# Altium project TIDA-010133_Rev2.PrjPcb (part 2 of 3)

## Sheet 3_BUF802_OFFSET_TRIGGER.SchDoc: 3_BUF802_OFFSET_TRIGGER
size 431 x 279 mm; Date: Not shown in title block; ApprovedBy: Not shown in title block; CheckedBy: Not shown in title block; Author: Not shown in title block; CompanyName: Not shown in title block; DrawnBy: Rob Stoneham; Engineer: Not shown in title block; Organization: Not shown in title block; Address1: Not shown in title block; Address2: Not shown in title block; Address3: Not shown in title block; Address4: Not shown in title block; DocumentNumber: 4; Revision: Use project parameter SCH_Rev; SheetNumber: 4; SheetTotal: 8; PageSetup: Record=PageOptions¦CenterHorizontal=True¦CenterVertical=True¦PrintScale=1.00¦XCorrection=1.00¦YCorrection=1.00¦PrintKind=0¦BorderSize=5000000¦LeftOffset=0¦BottomOffset=0¦Orientation=2¦PaperLength=1000¦PaperWidth=1000¦Scale=100¦PaperSource=15¦PrintQuality=600¦MediaType=1¦DitherType=10¦PaperKind=Letter¦PrintScaleMode=1
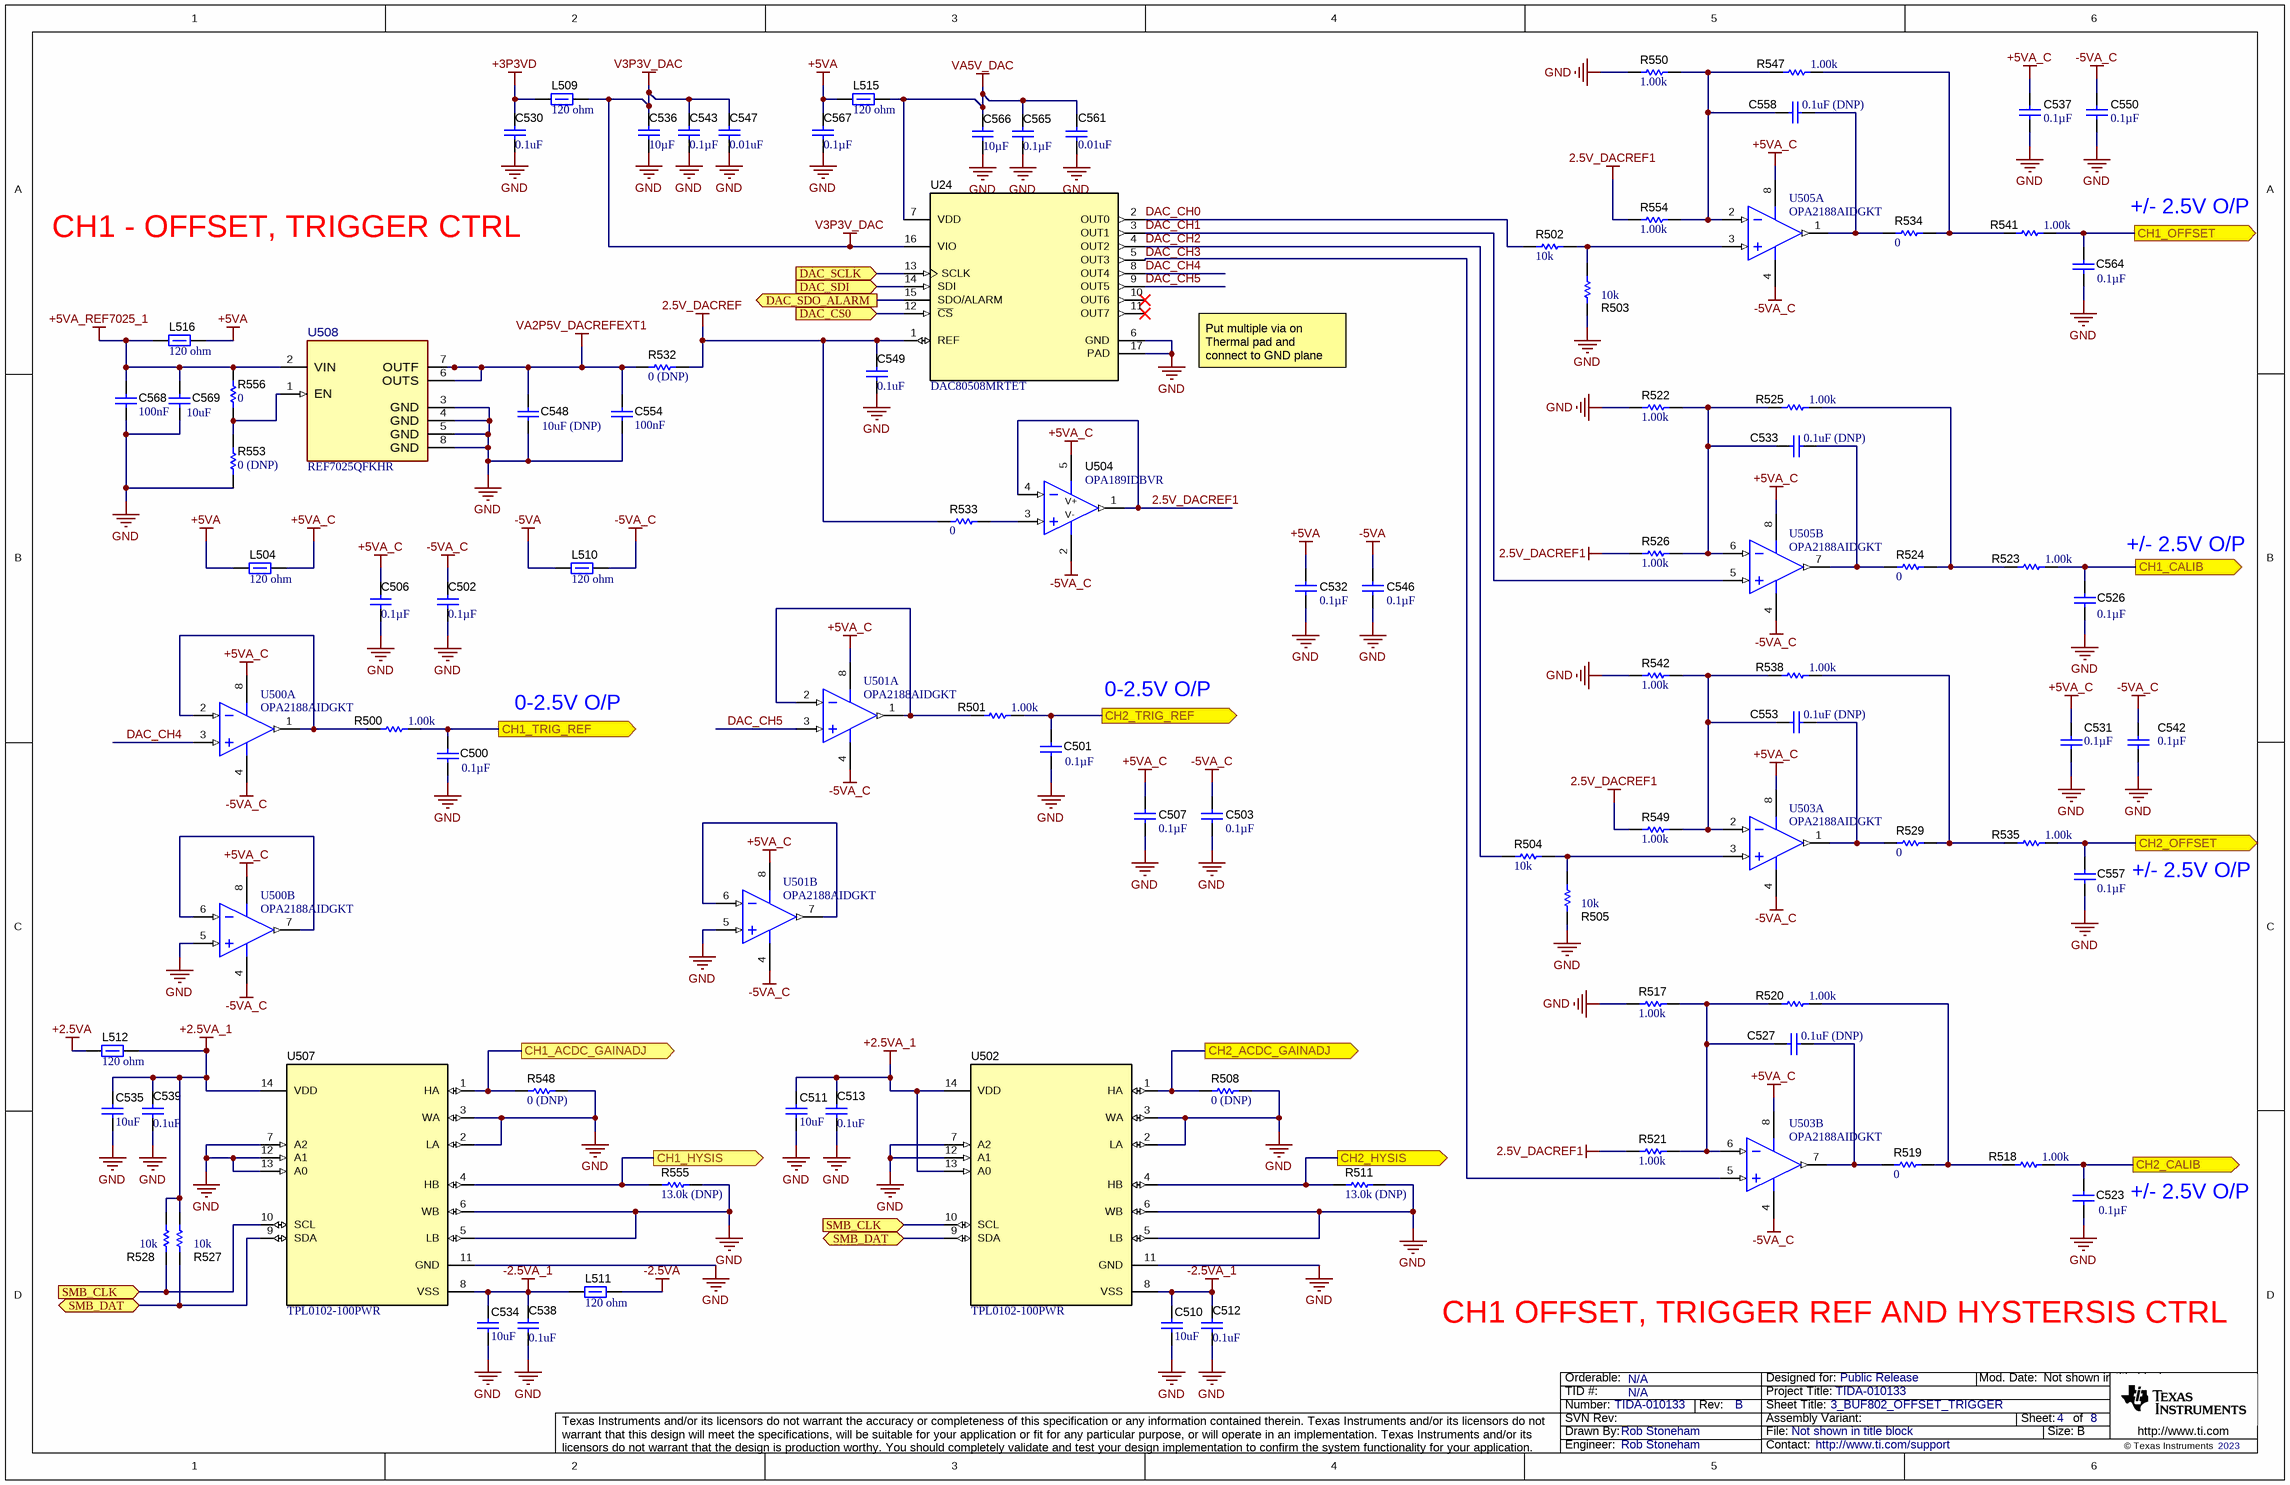
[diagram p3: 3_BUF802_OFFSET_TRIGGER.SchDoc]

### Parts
C500  ValueDisplayed: 0.1µF  [0402]  (hidden comment: 0402BB104KW500)
C501  ValueDisplayed: 0.1µF  [0402]  (hidden comment: 0402BB104KW500)
C502  ValueDisplayed: 0.1µF  [0402]  (hidden comment: 0402BB104KW500)
C503  ValueDisplayed: 0.1µF  [0402]  (hidden comment: 0402BB104KW500)
C506  ValueDisplayed: 0.1µF  [0402]  (hidden comment: 0402BB104KW500)
C507  ValueDisplayed: 0.1µF  [0402]  (hidden comment: 0402BB104KW500)
C510  ValueDisplayed: 10uF  [1206_190]  (hidden comment: C3216X7R1E106M160AE)
C511  ValueDisplayed: 10uF  [1206_190]  (hidden comment: C3216X7R1E106M160AE)
C512  ValueDisplayed: 0.1uF  [0603]  (hidden comment: CGA3E2X7R1H104K080AA)
C513  ValueDisplayed: 0.1uF  [0603]  (hidden comment: CGA3E2X7R1H104K080AA)
C523  ValueDisplayed: 0.1µF  [0402]  (hidden comment: 0402BB104KW500)
C526  ValueDisplayed: 0.1µF  [0402]  (hidden comment: 0402BB104KW500)
C527  ValueDisplayed: 0.1uF (DNP)  [0603]  (hidden comment: CGA3E2X7R1H104K080AA)
C530  ValueDisplayed: 0.1uF  [0603]  (hidden comment: CGA3E2X7R1H104K080AA)
C531  ValueDisplayed: 0.1µF  [0402]  (hidden comment: 0402BB104KW500)
C532  ValueDisplayed: 0.1µF  [0402]  (hidden comment: 0402BB104KW500)
C533  ValueDisplayed: 0.1uF (DNP)  [0603]  (hidden comment: CGA3E2X7R1H104K080AA)
C534  ValueDisplayed: 10uF  [1206_190]  (hidden comment: C3216X7R1E106M160AE)
C535  ValueDisplayed: 10uF  [1206_190]  (hidden comment: C3216X7R1E106M160AE)
C536  ValueDisplayed: 10µF  [0805_HV]  (hidden comment: CC0805KKX5R8BB106)
C537  ValueDisplayed: 0.1µF  [0402]  (hidden comment: 0402BB104KW500)
C538  ValueDisplayed: 0.1uF  [0603]  (hidden comment: CGA3E2X7R1H104K080AA)
C539  ValueDisplayed: 0.1uF  [0603]  (hidden comment: CGA3E2X7R1H104K080AA)
C542  ValueDisplayed: 0.1µF  [0402]  (hidden comment: 0402BB104KW500)
C543  ValueDisplayed: 0.1µF  [0402]  (hidden comment: 0402BB104KW500)
C546  ValueDisplayed: 0.1µF  [0402]  (hidden comment: 0402BB104KW500)
C547  ValueDisplayed: 0.01uF  [0402]  (hidden comment: GRM155R71H103KA88D)
C548  value 10uF (DNP)  [1206_180]  (hidden comment: C3216X7R1V106K160AC)
C549  ValueDisplayed: 0.1uF  [0603]  (hidden comment: CGA3E2X7R1H104K080AA)
C550  ValueDisplayed: 0.1µF  [0402]  (hidden comment: 0402BB104KW500)
C553  ValueDisplayed: 0.1uF (DNP)  [0603]  (hidden comment: CGA3E2X7R1H104K080AA)
C554  Cap_F: 100nF  [0603]  (hidden comment: C0603X104K4RACTU)
C557  ValueDisplayed: 0.1µF  [0402]  (hidden comment: 0402BB104KW500)
C558  ValueDisplayed: 0.1uF (DNP)  [0603]  (hidden comment: CGA3E2X7R1H104K080AA)
C561  ValueDisplayed: 0.01uF  [0402]  (hidden comment: GRM155R71H103KA88D)
C564  ValueDisplayed: 0.1µF  [0402]  (hidden comment: 0402BB104KW500)
C565  ValueDisplayed: 0.1µF  [0402]  (hidden comment: 0402BB104KW500)
C566  ValueDisplayed: 10µF  [0805_HV]  (hidden comment: CC0805KKX5R8BB106)
C567  ValueDisplayed: 0.1µF  [0402]  (hidden comment: 0402BB104KW500)
C568  Cap_F: 100nF  [0603]  (hidden comment: CGA3E2X7R1H104K080AA)
C569  ValueDisplayed: 10uF  [1206_180]  (hidden comment: C3216X7R1V106K160AC)
L504  ValueDisplayed: 120 ohm  [0603]  (hidden comment: BLM18SG121TN1D)
L509  ValueDisplayed: 120 ohm  [0603]  (hidden comment: BLM18SG121TN1D)
L510  ValueDisplayed: 120 ohm  [0603]  (hidden comment: BLM18SG121TN1D)
L511  ValueDisplayed: 120 ohm  [0603]  (hidden comment: BLM18SG121TN1D)
L512  ValueDisplayed: 120 ohm  [0603]  (hidden comment: BLM18SG121TN1D)
L515  ValueDisplayed: 120 ohm  [0603]  (hidden comment: BLM18SG121TN1D)
L516  ValueDisplayed: 120 ohm  [0603]  (hidden comment: BLM18SG121TN1D)
R500  ValueDisplayed: 1.00k  [0603]  (hidden comment: RC0603FR-071KL)
R501  ValueDisplayed: 1.00k  [0603]  (hidden comment: RC0603FR-071KL)
R502  ValueDisplayed: 10k  [0603]  (hidden comment: CRCW060310K0JNEA)
R503  ValueDisplayed: 10k  [0603]  (hidden comment: CRCW060310K0JNEA)
R504  ValueDisplayed: 10k  [0603]  (hidden comment: CRCW060310K0JNEA)
R505  ValueDisplayed: 10k  [0603]  (hidden comment: CRCW060310K0JNEA)
R508  ValueDisplayed: 0 (DNP)  [0603]  (hidden comment: CRCW06030000Z0EA)
R511  ValueDisplayed: 13.0k (DNP)  [0402L]  (hidden comment: CRCW040213K0FKED)
R517  ValueDisplayed: 1.00k  [0603]  (hidden comment: RC0603FR-071KL)
R518  ValueDisplayed: 1.00k  [0603]  (hidden comment: RC0603FR-071KL)
R519  ValueDisplayed: 0  [0603]  (hidden comment: RMCF0603ZT0R00)
R520  ValueDisplayed: 1.00k  [0603]  (hidden comment: RC0603FR-071KL)
R521  ValueDisplayed: 1.00k  [0603]  (hidden comment: RC0603FR-071KL)
R522  ValueDisplayed: 1.00k  [0603]  (hidden comment: RC0603FR-071KL)
R523  ValueDisplayed: 1.00k  [0603]  (hidden comment: RC0603FR-071KL)
R524  ValueDisplayed: 0  [0603]  (hidden comment: RMCF0603ZT0R00)
R525  ValueDisplayed: 1.00k  [0603]  (hidden comment: RC0603FR-071KL)
R526  ValueDisplayed: 1.00k  [0603]  (hidden comment: RC0603FR-071KL)
R527  ValueDisplayed: 10k  [0603]  (hidden comment: CRCW060310K0JNEA)
R528  ValueDisplayed: 10k  [0603]  (hidden comment: CRCW060310K0JNEA)
R529  ValueDisplayed: 0  [0603]  (hidden comment: RMCF0603ZT0R00)
R532  ValueDisplayed: 0 (DNP)  [0603]  (hidden comment: CRCW06030000Z0EA)
R533  ValueDisplayed: 0  [0603]  (hidden comment: CRCW06030000Z0EA)
R534  ValueDisplayed: 0  [0603]  (hidden comment: RMCF0603ZT0R00)
R535  ValueDisplayed: 1.00k  [0603]  (hidden comment: RC0603FR-071KL)
R538  ValueDisplayed: 1.00k  [0603]  (hidden comment: RC0603FR-071KL)
R541  ValueDisplayed: 1.00k  [0603]  (hidden comment: RC0603FR-071KL)
R542  ValueDisplayed: 1.00k  [0603]  (hidden comment: RC0603FR-071KL)
R547  ValueDisplayed: 1.00k  [0603]  (hidden comment: RC0603FR-071KL)
R548  ValueDisplayed: 0 (DNP)  [0603]  (hidden comment: CRCW06030000Z0EA)
R549  ValueDisplayed: 1.00k  [0603]  (hidden comment: RC0603FR-071KL)
R550  ValueDisplayed: 1.00k  [0603]  (hidden comment: RC0603FR-071KL)
R553  ValueDisplayed: 0 (DNP)  [0603]  (hidden comment: CRCW06030000Z0EA)
R554  ValueDisplayed: 1.00k  [0603]  (hidden comment: RC0603FR-071KL)
R555  ValueDisplayed: 13.0k (DNP)  [0402L]  (hidden comment: CRCW040213K0FKED)
R556  ValueDisplayed: 0  [0603]  (hidden comment: CRCW06030000Z0EA)
U24  DAC80508MRTET  [RTE0016D]
U500  OPA2188AIDGKT  [DGK0008A_N]  (parts A,B of 2)
U501  OPA2188AIDGKT  [DGK0008A_N]  (parts A,B of 2)
U502  TPL0102-100PWR  [PW0014A_N]
U503  OPA2188AIDGKT  [DGK0008A_N]  (parts A,B of 2)
U504  OPA189IDBVR  [DBV0005A_N]
U505  OPA2188AIDGKT  [DGK0008A_N]  (parts A,B of 2)
U507  TPL0102-100PWR  [PW0014A_N]
U508  REF7025QFKHR  [FKH0008A-MFG]

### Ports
CH1_ACDC_GAINADJ (out), CH1_CALIB (out), CH1_HYSIS (out), CH1_OFFSET (out), CH1_TRIG_REF (out), CH2_ACDC_GAINADJ (out), CH2_CALIB (out), CH2_HYSIS (out), CH2_OFFSET (out), CH2_TRIG_REF (out), DAC_CS0 (in), DAC_SCLK (in), DAC_SDI (in), DAC_SDO_ALARM (out), SMB_CLK (in), SMB_DAT (bidir)

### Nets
2.5V_DACREF: C549.1 R532.1 R533.2 U24.1(REF)
2.5V_DACREF1: R521.1 R526.1 R549.1 R554.1 U504.1(OUT) U504.4(IN-)
+2.5VA: L512.1
+2.5VA_1: C511.2 C513.1 C535.2 C539.1 L512.2 R527.2 R528.2 U502.13(A0) U502.14(VDD) U507.14(VDD)
+3P3VD: C530.1 L509.1
+5VA: C532.1 C567.1 L504.1 L515.1 L516.2
+5VA_C: C506.1 C507.1 C531.1 C537.1 L504.2 U500.8(V+) U501.8(V+) U503.8(V+) U504.5(V+) U505.8(V+)
+5VA_REF7025_1: C568.1 C569.1 L516.1 R556.2 U508.2(VIN)
-2.5VA: L511.2
-2.5VA_1: C510.2 C512.1 C534.2 C538.1 L511.1 U502.8(VSS) U507.8(VSS)
-5VA: C546.1 L510.1
-5VA_C: C502.1 C503.1 C542.1 C550.1 L510.2 U500.4(V-) U501.4(V-) U503.4(V-) U504.2(V-) U505.4(V-)
GND: C500.2 C501.2 C502.2 C503.2 C506.2 C507.2 C510.1 C511.1 C512.2 C513.2 C523.2 C526.2 C530.2 C531.2 C532.2 C534.1 C535.1 C536.2 C537.2 C538.2 C539.2 C542.2 C543.2 C546.2 C547.2 C548.2 C549.2 C550.2 C554.2 C557.2 C561.2 C564.2 C565.2 C566.2 C567.2 C568.2 C569.2 R503.1 R505.1 R508.2 R511.1 R517.1 R522.1 R542.1 R548.2 R550.1 R553.1 R555.1 U24.6(GND) U24.17(PAD) U500.5(IN_B+) U501.5(IN_B+) U502.2(LA) U502.3(WA) U502.5(LB) U502.6(WB) U502.7(A2) U502.11(GND) U502.12(A1) U507.2(LA) U507.3(WA) U507.5(LB) U507.6(WB) U507.7(A2) U507.11(GND) U507.12(A1) U507.13(A0) U508.3(GND) U508.4(GND) U508.5(GND) U508.8(GND)
V3P3V_DAC: C536.1 C543.1 C547.1 L509.2 U24.16(VIO)
VA2P5V_DACREFEXT1: C548.1 C554.1 R532.2 U508.6(OUTS) U508.7(OUTF)
VA5V_DAC: C561.1 C565.1 C566.1 L515.2 U24.7(VDD)
CH1_ACDC_GAINADJ: R548.1 U507.1(HA) ; port CH1_ACDC_GAINADJ
CH1_CALIB: C526.1 R523.2 ; port CH1_CALIB
CH1_HYSIS: R555.2 U507.4(HB) ; port CH1_HYSIS
CH1_OFFSET: C564.1 R541.2 ; port CH1_OFFSET
CH1_TRIG_REF: C500.1 R500.2 ; port CH1_TRIG_REF
CH2_ACDC_GAINADJ: R508.1 U502.1(HA) ; port CH2_ACDC_GAINADJ
CH2_CALIB: C523.1 R518.2 ; port CH2_CALIB
CH2_HYSIS: R511.2 U502.4(HB) ; port CH2_HYSIS
CH2_OFFSET: C557.1 R535.2 ; port CH2_OFFSET
CH2_TRIG_REF: C501.1 R501.2 ; port CH2_TRIG_REF
DAC_CH0: R502.2 U24.2(OUT0)
DAC_CH1: U24.3(OUT1) U505.5(IN_B+)
DAC_CH2: R504.2 U24.4(OUT2)
DAC_CH3: U24.5(OUT3) U503.5(IN_B+)
DAC_CH4: U24.8(OUT4) U500.3(IN_A+)
DAC_CH5: U24.9(OUT5) U501.3(IN_A+)
DAC_CS0: U24.12(~{CS}) ; port DAC_CS0
DAC_SCLK: U24.13(SCLK) ; port DAC_SCLK
DAC_SDI: U24.14(SDI) ; port DAC_SDI
DAC_SDO_ALARM: U24.15(SDO/ALARM) ; port DAC_SDO_ALARM
SMB_CLK: R528.1 U502.10(SCL) U507.10(SCL) ; port SMB_CLK
SMB_DAT: R527.1 U502.9(SDA) U507.9(SDA) ; port SMB_DAT
NetC527_1: C527.1 R517.2 R520.1 R521.2 U503.6(IN_B-)
NetC527_2: C527.2 R519.1 U503.7(OUT_B)
NetC533_1: C533.1 R522.2 R525.1 R526.2 U505.6(IN_B-)
NetC533_2: C533.2 R524.1 U505.7(OUT_B)
NetC553_1: C553.1 R538.1 R542.2 R549.2 U503.2(IN_A-)
NetC553_2: C553.2 R529.1 U503.1(OUT_A)
NetC558_1: C558.1 R547.1 R550.2 R554.2 U505.2(IN_A-)
NetC558_2: C558.2 R534.1 U505.1(OUT_A)
NetR500_1: R500.1 U500.1(OUT_A) U500.2(IN_A-)
NetR501_1: R501.1 U501.1(OUT_A) U501.2(IN_A-)
NetR502_1: R502.1 R503.2 U505.3(IN_A+)
NetR504_1: R504.1 R505.2 U503.3(IN_A+)
NetR518_1: R518.1 R519.2 R520.2
NetR523_1: R523.1 R524.2 R525.2
NetR529_2: R529.2 R535.1 R538.2
NetR533_1: R533.1 U504.3(IN+)
NetR534_2: R534.2 R541.1 R547.2
NetR553_2: R553.2 R556.1 U508.1(EN)
NetU500_6: U500.6(IN_B-) U500.7(OUT_B)
NetU501_6: U501.6(IN_B-) U501.7(OUT_B)

Not connected (* = marked no-connect by the designer): U24 10(OUT6)* 11(OUT7)*

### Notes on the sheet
- CH1 - OFFSET, TRIGGER CTRL
- +/- 2.5V O/P
- Put multiple via on Thermal pad and connect to GND plane
- 0-2.5V O/P
- (near C557) +/- 2.5V O/P
- (near C523) +/- 2.5V O/P
- CH1 OFFSET, TRIGGER REF AND HYSTERSIS CTRL

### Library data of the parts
C500-C503 C506 C507 C523 C526 C531 C532 C537 C542 C543 C546 C550 C557 C564 C565 C567 = CMP-0860983-1: CAP, CERM, 0.1 µF, 50 V,+/- 10%, X7R, 0402; Manufacturer: Passive Plus; TaMax_C: 125°C; VDC_V: 50V; U/M: EA; SizeY_mm: 0.5; TaMin_C: -55°C; SizeAreaWB_mm2: 3; Value: 0.1uF; AEC Qualified: N; SizeX_mm: 1; AEC Category: Q200; SizeZ_mm: 0.6; Cap_F: 100nF
C510 C511 C534 C535 = CMP-0008692-2: CAP, CERM, 10 uF, 25 V, +/- 20%, X7R, 1206_190; Manufacturer: TDK; Polarized: N; Value: 10uF; U/M: EA; Cap_F: 10µF; Value1: Unknown; VDC_V: 25V; TaMin_C: -55°C; TaMax_C: 125°C; Cap_Case: 1206; SizeArea_mm2: 5.12; SizeAreaWB_mm2: 10.92; SizeX_mm: 3.2; SizeY_mm: 1.6; SizeZ_mm: 1.9; AEC Category: Q200
C512 C513 C527 C530 C533 C538 C539 C549 C553 C558 = CMP-0007078-4: CAP, CERM, 0.1 uF, 50 V, +/- 10%, X7R, AEC-Q200 Grade 1, 0603; Manufacturer: TDK; Polarized: N; Value: 0.1uF; U/M: EA; Cap_F: 100nF; ESR_ohm: 29.6m; Value1: 0.0296 ohm; VDC_V: 50V; IRMS_A: 971.99mA; TaMin_C: -55°C; TaMax_C: 125°C; SizeArea_mm2: 1.28; SizeAreaWB_mm2: 4.68; SizeX_mm: 1.6; SizeY_mm: 0.8; SizeZ_mm: 1; AEC Category: Q200; AEC Qualified: Y
C536 C566 = CMP-0084177-1: CAP, CERM, 10 µF, 25 V,+/- 10%, X5R, 0805; Manufacturer: Yageo; SizeAreaWB_mm2: 6.75; SizeArea_mm2: 2.5; AEC Qualified: N; AEC Category: Q200; Value: 10uF; TaMax_C: 85°C; SizeZ_mm: 1.45; TaMin_C: -55°C; VDC_V: 25V; SizeY_mm: 1.25; U/M: EA; SizeX_mm: 2; Cap_Case: 0805
C547 C561 = CMP-0006674-2: CAP, CERM, 0.01 uF, 50 V, +/- 10%, X7R, 0402; Manufacturer: MuRata; TaMin_C: -55°C; Polarized: N; SizeAreaWB_mm2: 3; Value1: Unknown; U/M: EA; Value: 0.01uF; TaMax_C: 125°C; SizeZ_mm: 0.6; SizeX_mm: 1; SizeY_mm: 0.5; Value2: 50V; Cap_F: 10nF; AEC Category: Q200
C548 = CMP-0008705-2: CAP, CERM, 10 uF, 35 V, +/- 10%, X7R, 1206; Manufacturer: TDK; TaMin_C: -55°C; Polarized: N; SizeAreaWB_mm2: 10.92; Value1: 0.002229 ohm; U/M: EA; TaMax_C: 125°C; SizeZ_mm: 1.8; SizeX_mm: 3.2; SizeY_mm: 1.6; Value2: 35V; SizeArea_mm2: 5.12; Cap_F: 10µF; AEC Category: Q200; ValueDisplayed: 10uF; ESR_ohm: 2.229m; IRMS_A: 4.8593A
C554 = CMP-0006980-4: CAP, CERM, 0.1 uF, 16 V, +/- 10%, X7R, 0603; Manufacturer: Kemet; TaMin_C: -55°C; Polarized: N; SizeAreaWB_mm2: 4.68; Value1: Unknown; U/M: EA; Value: 0.1uF; TaMax_C: 125°C; SizeZ_mm: 1; SizeX_mm: 1.6; SizeY_mm: 0.8; Value2: 16V; SizeArea_mm2: 1.28; AEC Category: Q200
C568 = CMP-0007078-4: CAP, CERM, 0.1 uF, 50 V, +/- 10%, X7R, AEC-Q200 Grade 1, 0603; Manufacturer: TDK; TaMin_C: -55°C; ESR_ohm: 29.6m; Polarized: N; SizeAreaWB_mm2: 4.68; Value1: 0.0296 ohm; U/M: EA; Value: 0.1uF; TaMax_C: 125°C; SizeZ_mm: 1; SizeX_mm: 1.6; SizeY_mm: 0.8; Value2: 50V; SizeArea_mm2: 1.28; AEC Qualified: Y; IRMS_A: 971.99mA; AEC Category: Q200
C569 = CMP-0008705-2: CAP, CERM, 10 uF, 35 V, +/- 10%, X7R, 1206; Manufacturer: TDK; TaMin_C: -55°C; Polarized: N; SizeAreaWB_mm2: 10.92; Value1: 0.002229 ohm; U/M: EA; Value: 10uF; TaMax_C: 125°C; SizeZ_mm: 1.8; SizeX_mm: 3.2; SizeY_mm: 1.6; Value2: 35V; SizeArea_mm2: 5.12; Cap_F: 10µF; AEC Category: Q200; ESR_ohm: 2.229m; IRMS_A: 4.8593A
L504 L509-L512 L515 L516 = CMP-0003352-2: Ferrite Bead, 120 ohm @ 100 MHz, 3 A, 0603; Manufacturer: MuRata; Value: 120 ohm; Imax_A: 3A; DCR_ohm: 25m; Value1: 0.025 ohm; SizeAreaWB_mm2: 4.68; SizeArea_mm2: 1.28; SizeX_mm: 1.6; SizeY_mm: 0.8; SizeZ_mm: 1; ZTyp@100MHz_Ohm: 120
R500 R501 R517 R518 R520-R523 R525 R526 R535 R538 R541 R542 R547 R549 R550 R554 = CMP-0022895-5: RES, 1.00 k, 1%, 0.1 W, 0603; Manufacturer: Yageo; Power_W: 100mW; TempCo: 100 ppm/C; Value_Code: 1k00; Value: 1.00k; EIA_Code: E96; Res_ohm: 1k; SizeX_mm: 1.6; SizeY_mm: 0.8; SizeZ_mm: 1; Value2: 0.1W; SizeArea_mm2: 1.28; AEC Qualified: N; VDC_V: 75V; AEC Category: Q200; SizeAreaWB_mm2: 4.68
R502-R505 R527 R528 = CMP-0025701-4: RES, 10 k, 5%, 0.1 W, AEC-Q200 Grade 0, 0603; Manufacturer: Vishay-Dale; Value: 10k; Value_Code: 10k0; Power_W: 100mW; Value2: 0.1W; VDC_V: 75V; TempCo: 200 ppm/C; SizeArea_mm2: 1.28; SizeX_mm: 1.6; SizeY_mm: 0.8; SizeZ_mm: 1; EIA_Code: E24; AEC Category: Q200; AEC Qualified: Y; AEC Grade: 0
R508 R548 = CMP-0025697-4: RES, 0, 5%, 0.1 W, AEC-Q200 Grade 0, 0603; Manufacturer: Vishay-Dale; Power_W: 100mW; TempCo: 200 ppm/C; Value_Code: 0000; Value: 0; EIA_Code: E24; SizeX_mm: 1.6; SizeY_mm: 0.8; SizeZ_mm: 1; Value2: 0.1W; SizeArea_mm2: 1.28; AEC Qualified: Y; VDC_V: 75V; AEC Category: Q200
R511 R555 = CMP-0026003-3: RES, 13.0 k, 1%, 0.063 W, AEC-Q200 Grade 0, 0402; Manufacturer: Vishay-Dale; Power_W: 63mW; TempCo: 100 ppm/C; Value_Code: 13k0; Value: 13.0k; EIA_Code: E96; Res_ohm: 13k; SizeX_mm: 1; SizeY_mm: 0.5; SizeZ_mm: 0.6; Value2: 0.063W; AEC Qualified: Y; VDC_V: 50V; AEC Category: Q200; AEC Grade: 0
R519 R524 R529 R534 = CMP-0023343-3: RES, 0, 1%, 0.1 W, AEC-Q200 Grade 0, 0603; Manufacturer: Stackpole Electronics Inc; Power_W: 100mW; TempCo: ppm/C; U/M: EA; Value: 0; SizeX_mm: 1.6; SizeY_mm: 0.8; SizeZ_mm: 1; Value2: 0.1W; SizeArea_mm2: 1.28; AEC Qualified: Y; AEC Category: Q200
R532 R533 R553 R556 = CMP-0025697-4: RES, 0, 5%, 0.1 W, AEC-Q200 Grade 0, 0603; Manufacturer: Vishay-Dale; Value: 0; Value_Code: 0000; Power_W: 100mW; Value2: 0.1W; VDC_V: 75V; TempCo: 200 ppm/C; SizeArea_mm2: 1.28; SizeX_mm: 1.6; SizeY_mm: 0.8; SizeZ_mm: 1; EIA_Code: E24; AEC Category: Q200; AEC Qualified: Y
U24 = CMP-0084837-1: 8-Channel, True 16-Bit, SPI, Voltage-Output DAC With Precision Internal Reference, RTE0016D (WQFN-16); Alternate PartNumber: DAC80508MRTER; Alternate Manufacturer: Texas Instruments; CompType: IC; SizeAreaWB_mm2: 16; AEC Qualified: N; AEC Category: Q200; Rating: Catalog; SizeY_mm: 3; SizeZ_mm: 0.8; SizeArea_mm2: 9
U500 U501 U503 U505 = CMP-0040605-2: 0.03µV/°C, 6µV Vos, Low Noise, Rail-to-Rail Output, 36V Zero-Drift Operational Amplifier, DGK0008A (VSSOP-8); Manufacturer: Texas Instruments; Rating: Catalog; Vio (25C)(Max)(mV): 0.025; Number of Channels: 2; Slew Rate(Typ)(V/us): 0.8; IIB(Max)(pA): 850; Offset Drift(Typ)(uV/C): 0.03; Sub Family: High Supply Voltage Amplifier (>=30V), Low Noise Amp (<=10nV/rtHz), Low Offset Voltage Amplifier (<=500uV), Low Power Amp (<=500uA), Precision Amplifier, Zero Drift Precision Amplifier; CMRR(Min)(dB): 120; Total Supply Voltage(Max)(+5V is 5, +/-5V is 10): 36; Iq per channel(Max)(mA): 0.475; Total Supply Voltage(Min)(+5V is 5, +/-5V is 10): 4; Eco-Plan: Green (RoHS & no Sb/Br); Packing: SMALL T&R; AEC Category: Q200; AEC Qualified: N; CompType: IC; SizeAreaWB_mm2: 23.6; SizeArea_mm2: 14.7; SizeX_mm: 4.9; SizeY_mm: 3; SizeZ_mm: 1.1
U502 U507 = CMP-0066591-1: 256-Taps Dual-Channel Digital Potentiometer With I2C Interface and Nonvolatile Memory, PW0014A (TSSOP-14); Alternate Manufacturer: Texas Instruments; SizeAreaWB_mm2: 58.8; U/M: EA; SizeZ_mm: 1.2; SizeX_mm: 6.4; SizeY_mm: 5.0; SizeArea_mm2: 32.0; CompType: IC
U504 = CMP-0860961-1: 14MHz, MUX-friendly, low-noise, zero-drift, RRO, CMOS precision operational amplifier, DBV0005A (SOT-23-5); Alternate Manufacturer: Texas Instruments; Alternate PartNumber: OPA189IDBVT; SizeY_mm: 2.9; AEC Qualified: N; SizeX_mm: 2.8; SizeAreaWB_mm2: 14.82; CompType: IC; SizeZ_mm: 1.45; Rating: Catalog; AEC Category: Q200; SizeArea_mm2: 8.12
U508 = CMP-0091880-1: 2 ppm/°C Maximum Drift, 0.23 ppmp-p 1/f Noise, Precision Voltage Reference; Manufacturer: Texas Instruments; Number Of Outputs: 1; Output Voltage: 2.5V; Switching Topology: Buck; Output Type: Fixed; Max Supply Voltage: 18V; Nominal Supply Current: 4mA; SizeZ_mm: 1.6mm; TaMax_C: +125°C; TaMin_C: -40°C; Min Supply Voltage: 3V; AEC Qualified: No

## Sheet 4_BUF802_USBIF.SchDoc: 4_BUF802_USBIF
size 431 x 279 mm; Date: Not shown in title block; ApprovedBy: Not shown in title block; CheckedBy: Not shown in title block; Author: Not shown in title block; CompanyName: Not shown in title block; DrawnBy: Rob Stoneham; Engineer: Not shown in title block; Organization: Not shown in title block; Address1: Not shown in title block; Address2: Not shown in title block; Address3: Not shown in title block; Address4: Not shown in title block; DocumentNumber: 5; Revision: Use project parameter SCH_Rev; SheetNumber: 5; SheetTotal: 8; PageSetup: Record=PageOptions¦CenterHorizontal=True¦CenterVertical=True¦PrintScale=1.00¦XCorrection=1.00¦YCorrection=1.00¦PrintKind=0¦BorderSize=5000000¦LeftOffset=0¦BottomOffset=0¦Orientation=2¦PaperLength=1000¦PaperWidth=1000¦Scale=100¦PaperSource=15¦PrintQuality=600¦MediaType=1¦DitherType=10¦PaperKind=Letter¦PrintScaleMode=1
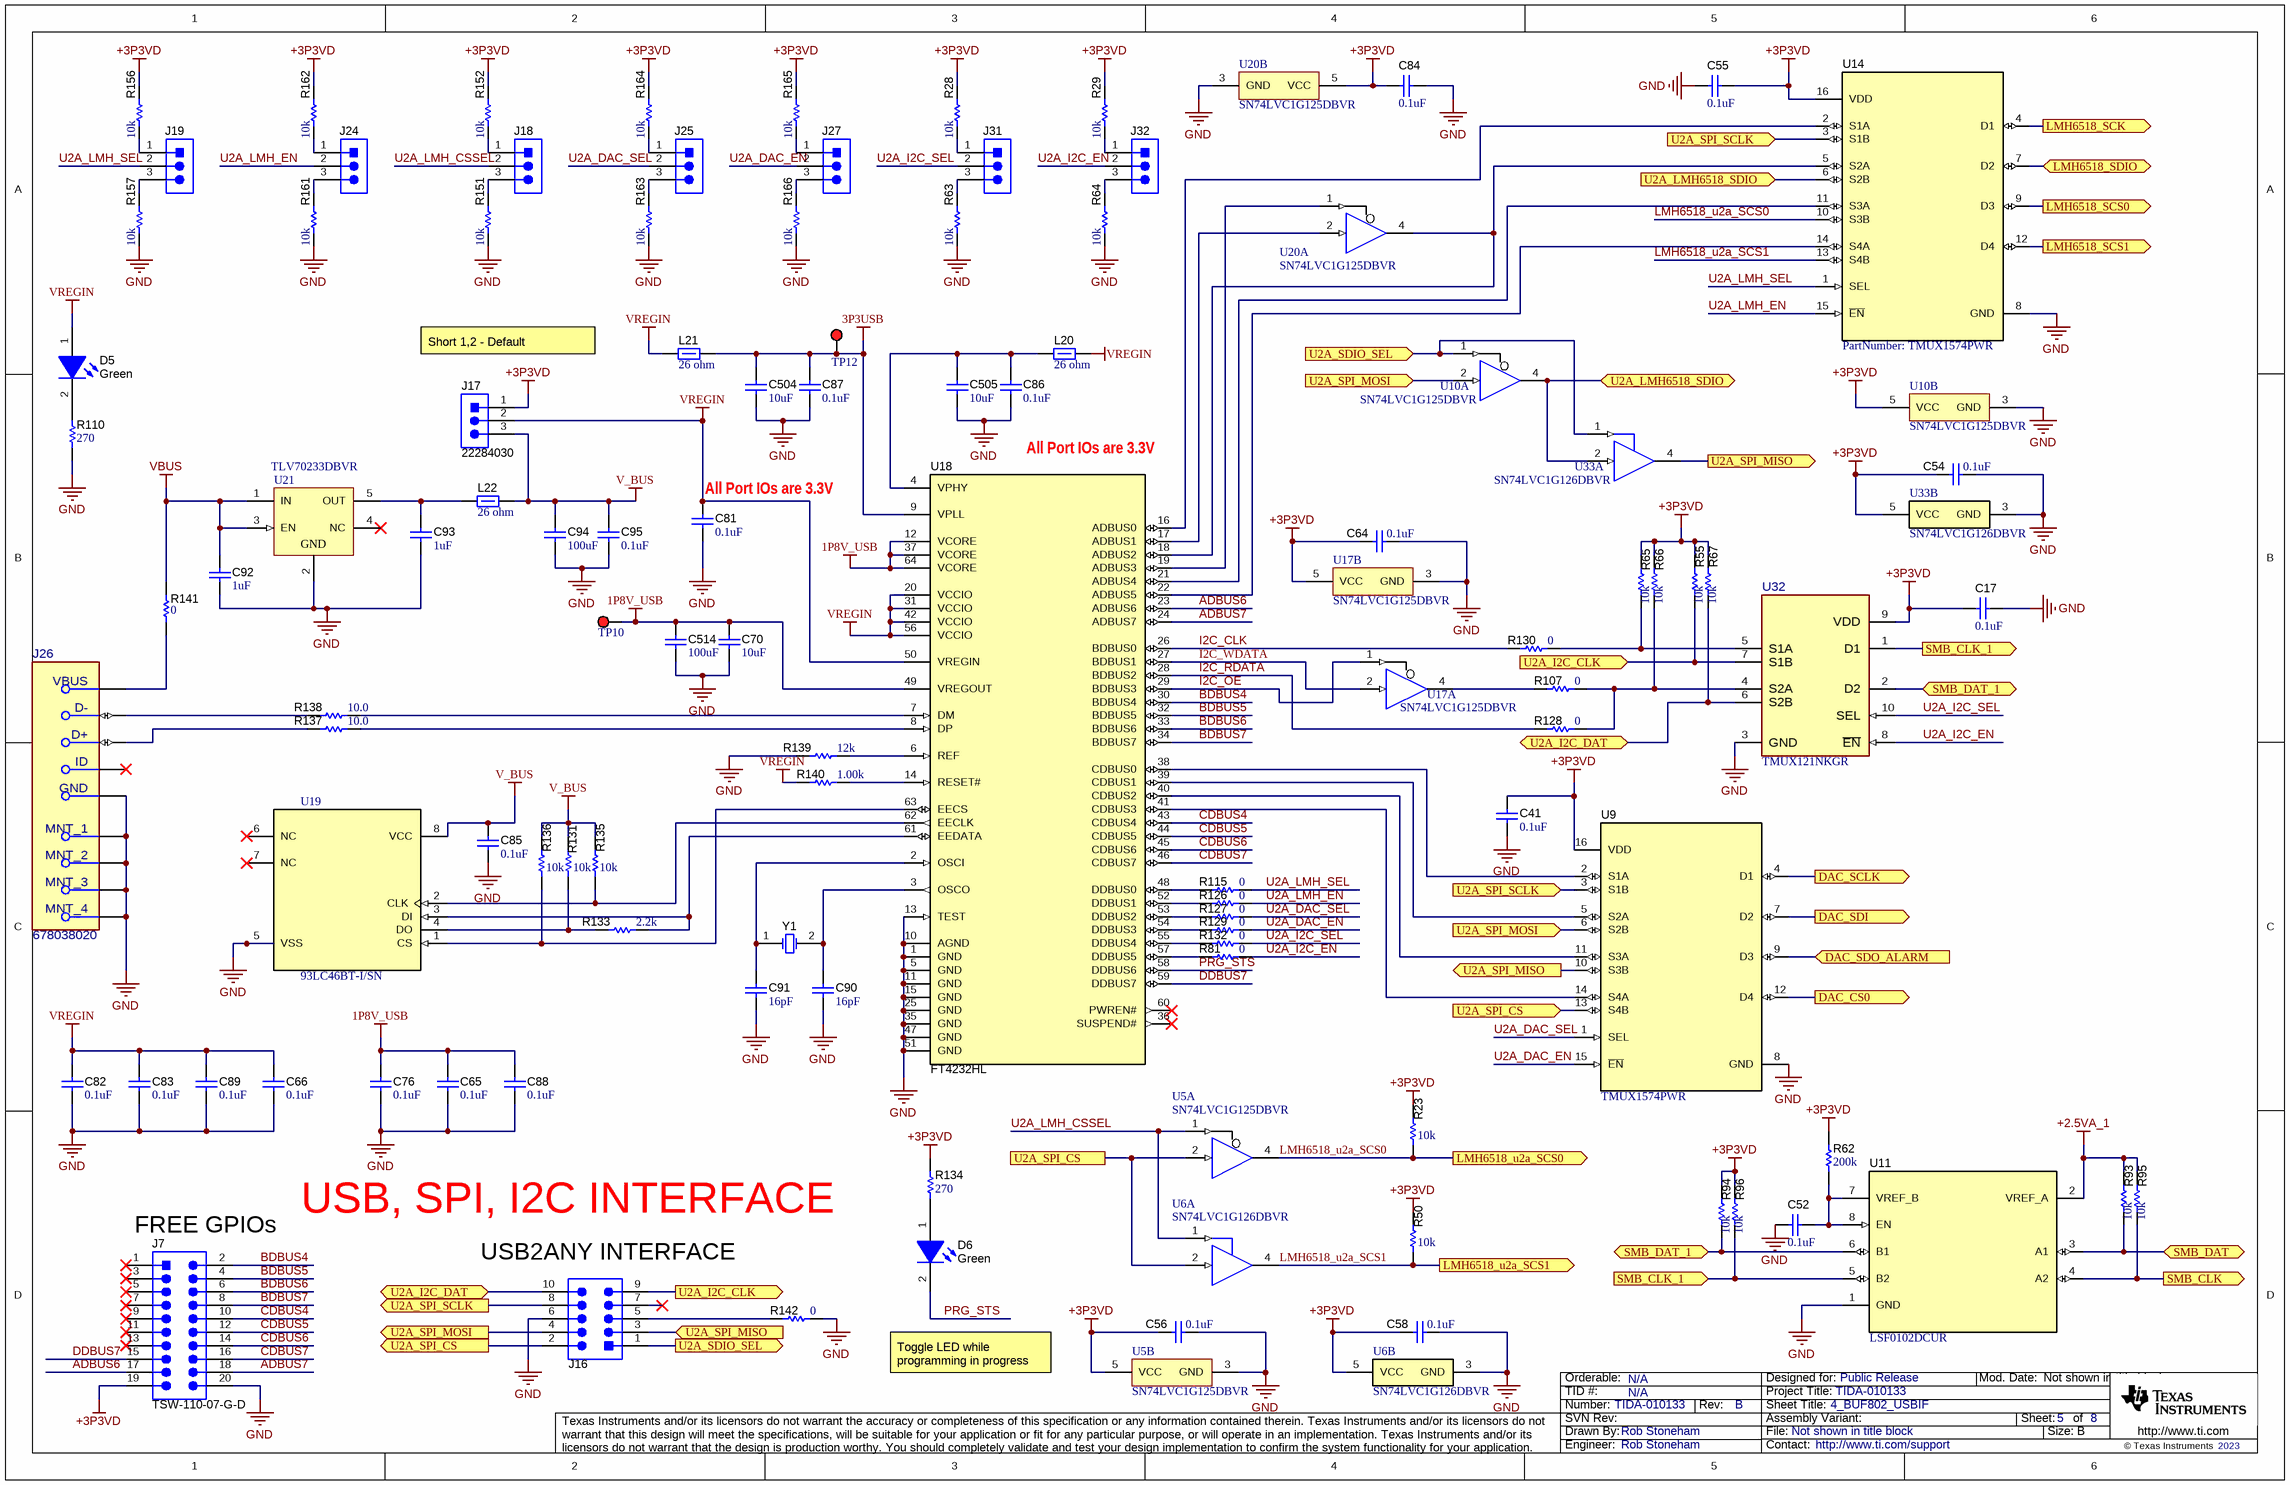
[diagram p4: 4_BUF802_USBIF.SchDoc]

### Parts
C17  ValueDisplayed: 0.1uF  [0603]  (hidden comment: C0603C104J3RACTU)
C41  ValueDisplayed: 0.1uF  [0603]  (hidden comment: C0603C104J3RACTU)
C52  ValueDisplayed: 0.1uF  [0603]  (hidden comment: C0603C104J3RACTU)
C54  ValueDisplayed: 0.1uF  [0603]  (hidden comment: C0603C104J3RACTU)
C55  ValueDisplayed: 0.1uF  [0603]  (hidden comment: C0603C104J3RACTU)
C56  ValueDisplayed: 0.1uF  [0603]  (hidden comment: C0603C104J3RACTU)
C58  ValueDisplayed: 0.1uF  [0603]  (hidden comment: C0603C104J3RACTU)
C64  ValueDisplayed: 0.1uF  [0603]  (hidden comment: C0603C104J3RACTU)
C65  ValueDisplayed: 0.1uF  [0603]  (hidden comment: C0603C104J3RACTU)
C66  ValueDisplayed: 0.1uF  [0603]  (hidden comment: C0603C104J3RACTU)
C70  ValueDisplayed: 10uF  [0603]  (hidden comment: GRM188R61A106ME69D)
C76  ValueDisplayed: 0.1uF  [0603]  (hidden comment: C0603C104J3RACTU)
C81  ValueDisplayed: 0.1uF  [0603]  (hidden comment: C0603C104J3RACTU)
C82  ValueDisplayed: 0.1uF  [0603]  (hidden comment: C0603C104J3RACTU)
C83  ValueDisplayed: 0.1uF  [0603]  (hidden comment: C0603C104J3RACTU)
C84  ValueDisplayed: 0.1uF  [0603]  (hidden comment: C0603C104J3RACTU)
C85  ValueDisplayed: 0.1uF  [0603]  (hidden comment: C0603C104J3RACTU)
C86  ValueDisplayed: 0.1uF  [0603]  (hidden comment: C0603C104J3RACTU)
C87  ValueDisplayed: 0.1uF  [0603]  (hidden comment: C0603C104J3RACTU)
C88  ValueDisplayed: 0.1uF  [0603]  (hidden comment: C0603C104J3RACTU)
C89  ValueDisplayed: 0.1uF  [0603]  (hidden comment: C0603C104J3RACTU)
C90  ValueDisplayed: 16pF  [0603]  (hidden comment: GRM1885C2A160JA01D)
C91  ValueDisplayed: 16pF  [0603]  (hidden comment: GRM1885C2A160JA01D)
C92  ValueDisplayed: 1uF  [0603]  (hidden comment: C1608X7R1C105K080AC)
C93  ValueDisplayed: 1uF  [0603]  (hidden comment: C1608X7R1C105K080AC)
C94  ValueDisplayed: 100uF  [1210_270]  (hidden comment: GRM32ER61A107ME20L)
C95  ValueDisplayed: 0.1uF  [0603]  (hidden comment: C0603C104J3RACTU)
C504  ValueDisplayed: 10uF  [0603]  (hidden comment: GRM188R61A106ME69D)
C505  ValueDisplayed: 10uF  [0603]  (hidden comment: GRM188R61A106ME69D)
C514  ValueDisplayed: 100uF  [1210_270]  (hidden comment: GRM32ER61A107ME20L)
D5  value Green  [LTST-C191_Green]  (hidden comment: LTST-C191TGKT)
D6  value Green  [LTST-C191_Green]  (hidden comment: LTST-C191TGKT)
J7  TSW-110-07-G-D  [TSW-110-07-G-D]
J16  61301021121  [WURTH_61301021121]  (value not drawn)
J17  22284030  [Molex_0022284030]
J18  22284030  [Molex_0022284030]  (value not drawn)
J19  22284030  [Molex_0022284030]  (value not drawn)
J24  22284030  [Molex_0022284030]  (value not drawn)
J25  22284030  [Molex_0022284030]  (value not drawn)
J26  678038020  [FP-678038020_CONN_USB-MFG]
J27  22284030  [Molex_0022284030]  (value not drawn)
J31  22284030  [Molex_0022284030]  (value not drawn)
J32  22284030  [Molex_0022284030]  (value not drawn)
L20  ValueDisplayed: 26 ohm  [0603]  (hidden comment: BLM18SG260TN1D)
L21  ValueDisplayed: 26 ohm  [0603]  (hidden comment: BLM18SG260TN1D)
L22  ValueDisplayed: 26 ohm  [0603]  (hidden comment: BLM18SG260TN1D)
R23  ValueDisplayed: 10k  [0603]  (hidden comment: CRCW060310K0JNEA)
R28  ValueDisplayed: 10k  [0603]  (hidden comment: CRCW060310K0JNEA)
R29  ValueDisplayed: 10k  [0603]  (hidden comment: CRCW060310K0JNEA)
R50  ValueDisplayed: 10k  [0603]  (hidden comment: CRCW060310K0JNEA)
R55  ValueDisplayed: 10k  [0603]  (hidden comment: CRCW060310K0JNEA)
R62  ValueDisplayed: 200k  [0603]  (hidden comment: CRCW0603200KFKEA)
R63  ValueDisplayed: 10k  [0603]  (hidden comment: CRCW060310K0JNEA)
R64  ValueDisplayed: 10k  [0603]  (hidden comment: CRCW060310K0JNEA)
R65  ValueDisplayed: 10k  [0603]  (hidden comment: CRCW060310K0JNEA)
R66  ValueDisplayed: 10k  [0603]  (hidden comment: CRCW060310K0JNEA)
R67  ValueDisplayed: 10k  [0603]  (hidden comment: CRCW060310K0JNEA)
R81  ValueDisplayed: 0  [0603]  (hidden comment: CRCW06030000Z0EA)
R93  ValueDisplayed: 10k  [0603]  (hidden comment: CRCW060310K0JNEA)
R94  ValueDisplayed: 10k  [0603]  (hidden comment: CRCW060310K0JNEA)
R95  ValueDisplayed: 10k  [0603]  (hidden comment: CRCW060310K0JNEA)
R96  ValueDisplayed: 10k  [0603]  (hidden comment: CRCW060310K0JNEA)
R107  ValueDisplayed: 0  [0603]  (hidden comment: CRCW06030000Z0EA)
R110  ValueDisplayed: 270  [0603]  (hidden comment: CRCW0603270RJNEA)
R115  ValueDisplayed: 0  [0603]  (hidden comment: CRCW06030000Z0EA)
R126  ValueDisplayed: 0  [0603]  (hidden comment: CRCW06030000Z0EA)
R127  ValueDisplayed: 0  [0603]  (hidden comment: CRCW06030000Z0EA)
R128  ValueDisplayed: 0  [0603]  (hidden comment: CRCW06030000Z0EA)
R129  ValueDisplayed: 0  [0603]  (hidden comment: CRCW06030000Z0EA)
R130  ValueDisplayed: 0  [0603]  (hidden comment: CRCW06030000Z0EA)
R131  ValueDisplayed: 10k  [0603]  (hidden comment: CRCW060310K0JNEA)
R132  ValueDisplayed: 0  [0603]  (hidden comment: CRCW06030000Z0EA)
R133  ValueDisplayed: 2.2k  [0603]  (hidden comment: CRCW06032K20JNEA)
R134  ValueDisplayed: 270  [0603]  (hidden comment: CRCW0603270RJNEA)
R135  ValueDisplayed: 10k  [0603]  (hidden comment: CRCW060310K0JNEA)
R136  ValueDisplayed: 10k  [0603]  (hidden comment: CRCW060310K0JNEA)
R137  ValueDisplayed: 10.0  [0603]  (hidden comment: CRCW060310R0FKEAHP)
R138  ValueDisplayed: 10.0  [0603]  (hidden comment: CRCW060310R0FKEAHP)
R139  value 12k  [0603]  (hidden comment: CRCW060312K0JNEA)
R140  ValueDisplayed: 1.00k  [0603]  (hidden comment: CRCW06031K00FKEA)
R141  value 0  [0603]  (hidden comment: CRCW06030000Z0EA)
R142  ValueDisplayed: 0  [0603]  (hidden comment: CRCW06030000Z0EA)
R151  ValueDisplayed: 10k  [0603]  (hidden comment: CRCW060310K0JNEA)
R152  ValueDisplayed: 10k  [0603]  (hidden comment: CRCW060310K0JNEA)
R156  ValueDisplayed: 10k  [0603]  (hidden comment: CRCW060310K0JNEA)
R157  ValueDisplayed: 10k  [0603]  (hidden comment: CRCW060310K0JNEA)
R161  ValueDisplayed: 10k  [0603]  (hidden comment: CRCW060310K0JNEA)
R162  ValueDisplayed: 10k  [0603]  (hidden comment: CRCW060310K0JNEA)
R163  ValueDisplayed: 10k  [0603]  (hidden comment: CRCW060310K0JNEA)
R164  ValueDisplayed: 10k  [0603]  (hidden comment: CRCW060310K0JNEA)
R165  ValueDisplayed: 10k  [0603]  (hidden comment: CRCW060310K0JNEA)
R166  ValueDisplayed: 10k  [0603]  (hidden comment: CRCW060310K0JNEA)
TP10  5000  [Keystone5000]  (value not drawn)
TP12  5000  [Keystone5000]  (value not drawn)
U5  SN74LVC1G125DBVR  [DBV0005A_L]  (parts A,B of 2)
U6  SN74LVC1G126DBVR  [DBV0005A_N]  (parts A,B of 2)
U9  TMUX1574PWR  [PW0016A_N]
U10  SN74LVC1G125DBVR  [DBV0005A_L]  (parts A,B of 2)
U11  LSF0102DCUR  [DCU0008A_N]
U14  TMUX1574PWR  [PW0016A_N]
U17  SN74LVC1G125DBVR  [DBV0005A_L]  (parts A,B of 2)
U18  FT4232HL  [LQFP64_L]
U19  93LC46BT-I/SN  [SOIC-8]
U20  SN74LVC1G125DBVR  [DBV0005A_L]  (parts A,B of 2)
U21  TLV70233DBVR  [DBV0005A_N]
U32  TMUX121NKGR  [NKG0010A-MFG]
U33  SN74LVC1G126DBVR  [DBV0005A_N]  (parts A,B of 2)
Y1  ABM3-12.000MHZ-D2Y-T  [XTAL_ABM3]  (value not drawn)

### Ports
DAC_CS0 (out), DAC_SCLK (out), DAC_SDI (out), DAC_SDO_ALARM (in), LMH6518_SCK (out), LMH6518_SCS0 (out), LMH6518_SCS1 (out), LMH6518_SDIO (bidir), LMH6518_u2a_SCS0 (out), LMH6518_u2a_SCS1 (out), SMB_CLK (out), SMB_CLK_1 (in), SMB_CLK_1 (out), SMB_DAT (bidir), SMB_DAT_1 (bidir), U2A_I2C_CLK (in), U2A_I2C_CLK (out), U2A_I2C_DAT (bidir), U2A_LMH6518_SDIO (bidir), U2A_LMH6518_SDIO (in), U2A_SDIO_SEL (in), U2A_SDIO_SEL (out), U2A_SPI_CS, U2A_SPI_CS (in), U2A_SPI_CS (out), U2A_SPI_MISO (in), U2A_SPI_MISO (out), U2A_SPI_MOSI (in), U2A_SPI_MOSI (out), U2A_SPI_SCLK (in), U2A_SPI_SCLK (out)

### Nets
1P8V_USB: C65.2 C70.1 C76.2 C88.2 C514.1 TP10.1 U18.12(VCORE) U18.37(VCORE) U18.49(VREGOUT) U18.64(VCORE)
3P3USB: C87.2 C504.1 L21.2 TP12.1 U18.9(VPLL)
+2.5VA_1: R93.2 R95.2 U11.2(VREF_A)
+3P3VD: C17.1 C41.1 C54.1 C55.1 C56.1 C58.1 C64.2 C84.2 J7.19 J17.1 R23.2 R28.2 R29.2 R50.2 R55.2 R62.2 R65.2 R66.2 R67.2 R94.2 R96.2 R134.2 R152.2 R156.2 R162.2 R164.2 R165.2 U5.5(VCC) U6.5(VCC) U9.16(VDD) U10.5(VCC) U14.16(VDD) U17.5(VCC) U20.5(VCC) U32.9(VDD) U33.5(VCC)
GND: C17.2 C41.2 C52.1 C54.2 C55.2 C56.2 C58.2 C64.1 C65.1 C66.1 C70.2 C76.1 C81.1 C82.1 C83.1 C84.1 C85.1 C86.1 C87.1 C88.1 C89.1 C90.2 C91.2 C92.2 C93.2 C94.2 C95.1 C504.2 C505.2 C514.2 J7.20 J16.6 J26.5(GND) J26.6(MNT_1) J26.7(MNT_2) J26.8(MNT_3) J26.9(MNT_4) R63.1 R64.1 R110.1 R139.2 R142.1 R151.1 R157.1 R161.1 R163.1 R166.1 U5.3(GND) U6.3(GND) U9.8(GND) U10.3(GND) U11.1(GND) U14.8(GND) U17.3(GND) U18.1(GND) U18.5(GND) U18.10(AGND) U18.11(GND) U18.13(TEST) U18.15(GND) U18.25(GND) U18.35(GND) U18.47(GND) U18.51(GND) U19.5(VSS) U20.3(GND) U21.2(GND) U32.3(GND) U33.3(GND)
V_BUS: C85.2 C94.1 C95.2 J17.3 L22.2 R131.2 R135.2 R136.2 U19.8(VCC)
VBUS: C92.1 R141.2 U21.1(IN) U21.3(EN)
VREGIN: C66.2 C81.2 C82.2 C83.2 C89.2 D5.1(A) J17.2 L20.2 L21.1 R140.1 U18.20(VCCIO) U18.31(VCCIO) U18.42(VCCIO) U18.50(VREGIN) U18.56(VCCIO)
ADBUS6: J7.17 U18.23(ADBUS6)
ADBUS7: J7.18 U18.24(ADBUS7)
BDBUS4: J7.2 U18.30(BDBUS4)
BDBUS5: J7.4 U18.32(BDBUS5)
BDBUS6: J7.6 U18.33(BDBUS6)
BDBUS7: J7.8 U18.34(BDBUS7)
CDBUS4: J7.10 U18.43(CDBUS4)
CDBUS5: J7.12 U18.44(CDBUS5)
CDBUS6: J7.14 U18.45(CDBUS6)
CDBUS7: J7.16 U18.46(CDBUS7)
DAC_CS0: U9.12(D4) ; port DAC_CS0
DAC_SCLK: U9.4(D1) ; port DAC_SCLK
DAC_SDI: U9.7(D2) ; port DAC_SDI
DAC_SDO_ALARM: U9.9(D3) ; port DAC_SDO_ALARM
DDBUS7: J7.15 U18.59(DDBUS7)
I2C_CLK: R130.1 U18.26(BDBUS0)
I2C_OE: U17.1(~{OE}) U18.29(BDBUS3)
I2C_RDATA: R128.1 U18.28(BDBUS2)
I2C_WDATA: U17.2(A) U18.27(BDBUS1)
LMH6518_SCK: U14.4(D1) ; port LMH6518_SCK
LMH6518_SCS0: U14.9(D3) ; port LMH6518_SCS0
LMH6518_SCS1: U14.12(D4) ; port LMH6518_SCS1
LMH6518_SDIO: U14.7(D2) ; port LMH6518_SDIO
LMH6518_u2a_SCS0: R23.1 U5.4(Y) U14.10(S3B) ; port LMH6518_u2a_SCS0
LMH6518_u2a_SCS1: R50.1 U6.4(Y) U14.13(S4B) ; port LMH6518_u2a_SCS1
PRG_STS: D6.2(K) U18.58(DDBUS6)
SMB_CLK: R95.1 U11.4(A2) ; port SMB_CLK
SMB_CLK_1: R96.1 U11.5(B2) U32.1(D1) ; port SMB_CLK_1
SMB_DAT: R93.1 U11.3(A1) ; port SMB_DAT
SMB_DAT_1: R94.1 U11.6(B1) U32.2(D2) ; port SMB_DAT_1
U2A_DAC_EN: J27.2 R129.2 U9.15(~{EN})
U2A_DAC_SEL: J25.2 R127.2 U9.1(SEL)
U2A_I2C_CLK: J16.9 R55.1 U32.7(S1B) ; port U2A_I2C_CLK
U2A_I2C_DAT: J16.10 R67.1 U32.6(S2B) ; port U2A_I2C_DAT
U2A_I2C_EN: J32.2 R81.2 U32.8(~{EN})
U2A_I2C_SEL: J31.2 R132.2 U32.10(SEL)
U2A_LMH6518_SDIO: U10.4(Y) U14.6(S2B) U33.2(A) ; port U2A_LMH6518_SDIO
U2A_LMH_CSSEL: J18.2 U5.1(~{OE}) U6.1(OE)
U2A_LMH_EN: J24.2 R126.2 U14.15(~{EN})
U2A_LMH_SEL: J19.2 R115.2 U14.1(SEL)
U2A_SDIO_SEL: J16.1 U10.1(~{OE}) U33.1(OE) ; port U2A_SDIO_SEL
U2A_SPI_CS: J16.2 U5.2(A) U6.2(A) U9.13(S4B) ; port U2A_SPI_CS
U2A_SPI_MISO: J16.3 U9.10(S3B) U33.4(Y) ; port U2A_SPI_MISO
U2A_SPI_MOSI: J16.4 U9.6(S2B) U10.2(A) ; port U2A_SPI_MOSI
U2A_SPI_SCLK: J16.8 U9.3(S1B) U14.3(S1B) ; port U2A_SPI_SCLK
NetC52_2: C52.2 R62.1 U11.7(VREF_B) U11.8(EN)
NetC86_2: C86.2 C505.1 L20.1 U18.4(VPHY)
NetC90_1: C90.1 U18.3(OSCO) Y1.2(OSC2)
NetC91_1: C91.1 U18.2(OSCI) Y1.1(OSC1)
NetC93_1: C93.1 L22.1 U21.5(OUT)
NetD5_2: D5.2(K) R110.2
NetD6_1: D6.1(A) R134.1
NetJ16_5: J16.5 R142.2
NetJ18_1: J18.1 R152.1
NetJ18_3: J18.3 R151.2
NetJ19_1: J19.1 R156.1
NetJ19_3: J19.3 R157.2
NetJ24_1: J24.1 R162.1
NetJ24_3: J24.3 R161.2
NetJ25_1: J25.1 R164.1
NetJ25_3: J25.3 R163.2
NetJ26_1: J26.1(VBUS) R141.1
NetJ26_2: J26.2(D-) R138.1
NetJ26_3: J26.3(D+) R137.1
NetJ27_1: J27.1 R165.1
NetJ27_3: J27.3 R166.2
NetJ31_1: J31.1 R28.1
NetJ31_3: J31.3 R63.2
NetJ32_1: J32.1 R29.1
NetJ32_3: J32.3 R64.2
NetR65_1: R65.1 R130.2 U32.5(S1A)
NetR66_1: R66.1 R107.2 R128.2 U32.4(S2A)
NetR81_1: R81.1 U18.57(DDBUS5)
NetR107_1: R107.1 U17.4(Y)
NetR115_1: R115.1 U18.48(DDBUS0)
NetR126_1: R126.1 U18.52(DDBUS1)
NetR127_1: R127.1 U18.53(DDBUS2)
NetR129_1: R129.1 U18.54(DDBUS3)
NetR131_1: R131.1 R133.1 U19.4(DO)
NetR132_1: R132.1 U18.55(DDBUS4)
NetR133_2: R133.2 U18.61(EEDATA) U19.3(DI)
NetR135_1: R135.1 U18.62(EECLK) U19.2(CLK)
NetR136_1: R136.1 U18.63(EECS) U19.1(CS)
NetR137_2: R137.2 U18.8(DP)
NetR138_2: R138.2 U18.7(DM)
NetR139_1: R139.1 U18.6(REF)
NetR140_2: R140.2 U18.14(RESET#)
NetU9_2: U9.2(S1A) U18.38(CDBUS0)
NetU9_5: U9.5(S2A) U18.39(CDBUS1)
NetU9_11: U9.11(S3A) U18.40(CDBUS2)
NetU9_14: U9.14(S4A) U18.41(CDBUS3)
NetU14_2: U14.2(S1A) U18.16(ADBUS0)
NetU14_5: U14.5(S2A) U18.18(ADBUS2) U20.4(Y)
NetU14_11: U14.11(S3A) U18.21(ADBUS4)
NetU14_14: U14.14(S4A) U18.22(ADBUS5)
NetU18_17: U18.17(ADBUS1) U20.2(A)
NetU18_19: U18.19(ADBUS3) U20.1(~{OE})

Not connected (* = marked no-connect by the designer): J7 1* 3* 5* 7* 9* 11* 13*; J16 7*; J26 4(ID)*; U18 36(SUSPEND#)* 60(PWREN#)*; U19 6(NC)* 7(NC)*; U21 4(NC)*

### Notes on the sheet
- Short 1,2 - Default
- (near C81) All Port IOs are 3.3V
- All Port IOs are 3.3V
- (near J7) FREE GPIOs
- USB, SPI, I2C INTERFACE
- (near J16) USB2ANY INTERFACE
- Toggle LED while programming in progress

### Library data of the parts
C17 C41 C52 C54-C56 C58 C64-C66 C76 C81-C89 C95 = CMP-0006856-6: CAP, CERM, 0.1 uF, 25 V, +/- 5%, X7R, 0603; Manufacturer: Kemet; Polarized: N; TaMax_C: 125°C; TaMin_C: -55°C; VDC_V: 25V; Cap_F: 100nF; Value: 0.1uF; Value1: Unknown; U/M: EA; SizeAreaWB_mm2: 4.68; SizeZ_mm: 1; SizeX_mm: 1.6; SizeY_mm: 0.8; SizeArea_mm2: 1.28; AEC Category: Q200
C70 C504 C505 = CMP-0007318-5: CAP, CERM, 10 uF, 10 V, +/- 20%, X5R, 0603; Manufacturer: MuRata; Polarized: N; Value: 10uF; U/M: EA; Cap_F: 10µF; Value1: Unknown; VDC_V: 10V; TaMin_C: -55°C; TaMax_C: 85°C; SizeArea_mm2: 1.28; SizeAreaWB_mm2: 4.68; SizeX_mm: 1.6; SizeY_mm: 0.8; SizeZ_mm: 1; AEC Category: Q200
C90 C91 = CMP-0007249-4: CAP, CERM, 16 pF, 100 V, +/- 5%, C0G/NP0, 0603; Manufacturer: MuRata; Polarized: N; Value: 16pF; U/M: EA; Value1: Unknown; VDC_V: 100V; TaMin_C: -55°C; TaMax_C: 125°C; SizeArea_mm2: 1.28; SizeAreaWB_mm2: 4.68; SizeX_mm: 1.6; SizeY_mm: 0.8; SizeZ_mm: 1; AEC Category: Q200
C92 C93 = CMP-0007037-4: CAP, CERM, 1 uF, 16 V, +/- 10%, X7R, 0603; Manufacturer: TDK; Polarized: N; Value: 1uF; U/M: EA; Cap_F: 1µF; ESR_ohm: 5.7m; Value1: 0.0057 ohm; VDC_V: 16V; TaMin_C: -55°C; TaMax_C: 125°C; SizeArea_mm2: 1.28; SizeAreaWB_mm2: 4.68; SizeX_mm: 1.6; SizeY_mm: 0.8; SizeZ_mm: 1; AEC Category: Q200
C94 C514 = CMP-0009206-2: CAP, CERM, 100 uF, 10 V, +/- 20%, X5R, 1210; Manufacturer: MuRata; Polarized: N; Value: 100uF; U/M: EA; Cap_F: 100µF; Value1: Unknown; VDC_V: 10V; TaMin_C: -55°C; TaMax_C: 85°C; Cap_Case: 1210; SizeArea_mm2: 8; SizeAreaWB_mm2: 14.7; SizeX_mm: 3.2; SizeY_mm: 2.5; SizeZ_mm: 2.7; AEC Category: Q200
D5 D6 = CMP-0002891-3: LED, Green, SMD; Manufacturer: Lite-On; Type: InGaN; Vf_V: 3.2V; Io_A: 20mA; Value1: W
J7 = CMP-0075421-2: Header, 100mil, 10x2, Gold, TH; Manufacturer: Samtec; Pitch_mm: 2.54; Cert_VDE: N; Gender: Male; Cert_CSA: Y; Voltage_V: 550V; Green_REACh: Passed; Current_A: 6.3A; Green_Lifecycle: Active; Row_Count: 2
J16 = CMP-0054806-3: Header, 2.54 mm, 5x2, Gold, TH; Manufacturer: Wurth Elektronik; Pitch_mm: 2.54; Gender: Male; Shrouded: N; Row_Count: 2; Current_A: 3A; Voltage_V: 250V; Cert_UL: Y; Green_Lifecycle: Active; Green_REACh: Passed
J17-J19 J24 J25 J27 J31 J32 = CMP-0078237-1: Header, 2.54mm, 3x1, Tin, TH; Manufacturer: Molex; Pitch_mm: 2.54; Gender: Male; Cert_CSA: Y; Current_A: 4A; Voltage_V: 500V; Shrouded: N; Row_Count: 1
J26 = CMP-0088148-1: MOLEX 67803-8020 MINI USB, 2.0 OTG TYPE AB, RCPT, TH; Current_A: 1A; Shrouded: true; Voltage_V: 30V; ContactFinish: Gold,Nickel
L20-L22 = CMP-0003354-2: Ferrite Bead, 26 ohm @ 100 MHz, 6 A, 0603; Manufacturer: MuRata; Value: 26 ohm; Imax_A: 6A; DCR_ohm: 7m; Value1: 0.007 ohm; SizeAreaWB_mm2: 4.68; SizeArea_mm2: 1.28; SizeX_mm: 1.6; SizeY_mm: 0.8; SizeZ_mm: 1; ZTyp@100MHz_Ohm: 26
R23 R28 R29 R50 R55 R63-R67 R93-R96 R131 R135 R136 R151 R152 R156 R157 R161-R166 = CMP-0025701-4: as R502 on sheet 3_BUF802_OFFSET_TRIGGER
R62 = CMP-0022200-4: RES, 200 k, 1%, 0.1 W, AEC-Q200 Grade 0, 0603; Manufacturer: Vishay-Dale; Power_W: 100mW; TempCo: 100 ppm/C; Value: 200k; EIA_Code: E96; SizeX_mm: 1.6; SizeY_mm: 0.8; SizeZ_mm: 1; Value2: 0.1W; SizeArea_mm2: 1.28; AEC Qualified: Y; VDC_V: 75V; AEC Category: Q200; AEC Grade: 0
R81 R107 R115 R126-R130 R132 R142 = CMP-0025697-4: as R532 on sheet 3_BUF802_OFFSET_TRIGGER
R110 R134 = CMP-0025765-4: RES, 270, 5%, 0.1 W, AEC-Q200 Grade 0, 0603; Manufacturer: Vishay-Dale; Value: 270; Value_Code: 270R; Power_W: 100mW; Value2: 0.1W; VDC_V: 75V; TempCo: 200 ppm/C; SizeArea_mm2: 1.28; SizeX_mm: 1.6; SizeY_mm: 0.8; SizeZ_mm: 1; EIA_Code: E24; AEC Category: Q200; AEC Qualified: Y; AEC Grade: 0
R133 = CMP-0025769-4: RES, 2.2 k, 5%, 0.1 W, AEC-Q200 Grade 0, 0603; Manufacturer: Vishay-Dale; Value: 2.2k; Value_Code: 2k20; Power_W: 100mW; Value2: 0.1W; VDC_V: 75V; TempCo: 200 ppm/C; SizeArea_mm2: 1.28; SizeX_mm: 1.6; SizeY_mm: 0.8; SizeZ_mm: 1; EIA_Code: E24; AEC Category: Q200; AEC Qualified: Y; AEC Grade: 0
R137 R138 = CMP-0022004-4: RES, 10.0, 1%, 0.25 W, AEC-Q200 Grade 0, 0603; Manufacturer: Vishay-Dale; Value: 10.0; Res_ohm: 10; Value_Code: 10R0; Power_W: 250mW; Value2: 0.25W; VDC_V: 75V; TempCo: 100 ppm/C; SizeArea_mm2: 1.28; SizeX_mm: 1.6; SizeY_mm: 0.8; SizeZ_mm: 1; EIA_Code: E96; AEC Category: Q200; AEC Qualified: Y; AEC Grade: 0
R139 = CMP-0025711-4: RES, 12 k, 5%, 0.1 W, AEC-Q200 Grade 0, 0603; Manufacturer: Vishay-Dale; VDC_V: 75V; Power_W: 100mW; Value_Code: 12k0; Value2: 0.1W; EIA_Code: E24; TempCo: 200 ppm/C; SizeX_mm: 1.6; SizeY_mm: 0.8; SizeZ_mm: 1; SizeArea_mm2: 1.28; AEC Qualified: Y; AEC Category: Q200; AEC Grade: 0
R140 = CMP-0022109-5: RES, 1.00 k, 1%, 0.1 W, AEC-Q200 Grade 0, 0603; Manufacturer: Vishay-Dale; Value: 1.00k; Res_ohm: 1k; Value_Code: 1k00; Power_W: 100mW; Value2: 0.1W; VDC_V: 75V; TempCo: 100 ppm/C; SizeArea_mm2: 1.28; SizeX_mm: 1.6; SizeY_mm: 0.8; SizeZ_mm: 1; EIA_Code: E96; AEC Category: Q200; AEC Qualified: Y; AEC Grade: 0
R141 = CMP-0025697-4: RES, 0, 5%, 0.1 W, AEC-Q200 Grade 0, 0603; Manufacturer: Vishay-Dale; VDC_V: 75V; Power_W: 100mW; Value_Code: 0000; Value2: 0.1W; EIA_Code: E24; TempCo: 200 ppm/C; SizeX_mm: 1.6; SizeY_mm: 0.8; SizeZ_mm: 1; SizeArea_mm2: 1.28; AEC Qualified: Y; AEC Category: Q200
TP10 TP12 = CMP-0055137-2: Test Point, Miniature, Red, TH; Manufacturer: Keystone Electronics; ContactFinish: Silver; CNHeader: FALSE; Green_Lifecycle: Active; Green_REACh: Passed; CT: TRUE
U5 U10 U17 U20 = CMP-0051300-2: Single Bus Buffer Gate With 3-State Outputs, DBV0005A, LARGE T&R; Manufacturer: Texas Instruments; CompType: IC; VCC(Min)(V): 1.65; Sub-Family: Non-Inverting Buffer/Driver; tpd @ Nom Voltage(Max)(ns): 9,5.5,4.5,4; Input Type: CMOS/TTL; ICC @ Nom Voltage(Max)(mA): 0.01; Schmitt Trigger: No; Voltage(Nom)(V): 1.8,2.5,3.3,5; F @ Nom Voltage(Max)(Mhz): 150; Output Drive (IOL/IOH)(Max)(mA): 32/-32; 3-State Output: Yes; Output Type: CMOS; Bits(#): 1; Rating: Catalog; Technology Family: LVC; Logic: True; VCC(Max)(V): 5.5; AEC Category: Q200; AEC Qualified: N
U6 U33 = CMP-0052003-3: Single Bus Buffer Gate With 3-State Outputs, DBV0005A (SOT-23-5); Manufacturer: Texas Instruments; Bits(#): 1; F @ Nom Voltage(Max)(Mhz): 150; VCC(Min)(V): 1.65; Input Type: CMOS/TTL; Voltage(Nom)(V): 1.8,2.5,3.3,5; Output Type: CMOS; ICC @ Nom Voltage(Max)(mA): 0.01; Logic: True; VCC(Max)(V): 5.5; Schmitt Trigger: No; 3-State Output: Yes; tpd @ Nom Voltage(Max)(ns): 8,5.5,4.5,4; Rating: Catalog; Output Drive (IOL/IOH)(Max)(mA): 32/-32; AEC Category: Q200; AEC Qualified: N; CompType: IC; SizeAreaWB_mm2: 14.82; SizeArea_mm2: 8.12; SizeX_mm: 2.8; SizeY_mm: 2.9; SizeZ_mm: 1.45
U9 U14 = CMP-0086166-2: Low-capacitance, 2:1 (SPDT) 4-channel, powered-off protection switch with 1.8 V logic, PW0016A (TSSOP-16); Alternate Manufacturer: Texas Instruments; AEC Qualified: N; Rating: Catalog; SizeZ_mm: 1.2; CompType: IC; SizeArea_mm2: 32; AEC Category: Q200; SizeY_mm: 5; SizeAreaWB_mm2: 58.8; SizeX_mm: 6.4
U11 = CMP-0066433-2: Dual Bidirectional Multi-Voltage Level Translator, DCU0008A (VSSOP-8); Alternate Manufacturer: Texas Instruments; Green_Lifecycle: Active; SizeAreaWB_mm2: 12.6; Green_REACh: Passed; SizeZ_mm: 0.9; SizeX_mm: 3.2; SizeY_mm: 2.0; SizeArea_mm2: 6.4; CompType: IC; AEC Category: Q200; AEC Qualified: N; Rating: Catalog
U18 = CMP-0004747-1: Quad High Speed USB to Multipurpose UART/MPSSE IC; Manufacturer: FTDI
U19 = CMP-0005249-2: 1K Microwire Compatible Serial EEPROM; Manufacturer: Microchip; SizeAreaWB_mm2: 55.131; SizeArea_mm2: 29.351; SizeX_mm: 5.99; SizeY_mm: 4.9; SizeZ_mm: 1.75
U21 = CMP-0035516-1: Single Output LDO, 300 mA, Fixed 3.3 V Output, 2 to 5.5 V Input, with Low IQ, 5-pin SOT-23 (DBV), -40 to 125 degC, Green (RoHS & no Sb/Br); Manufacturer: Texas Instruments; Vout Adj(Max)(V): 3.3; SubFamily: Single Channel LDO; Vin(Max)(V): 5.5; Accuracy(%): 2; Iout(Max)(A): 0.3; Vdo(Typ)(mV): 220; Iq(Typ)(mA): 0.03
U32 = CMP-0122684-1: 2-pF, 3.3-V, 2:1 (SPDT), 2-channel, switch with 1.8-V compatible logic; Manufacturer: Texas Instruments; SizeZ_mm: 0.55mm; AEC Qualified: No; -3Db Bandwith: 3GHz; Max Supply Voltage: 3.6V; Min Supply Voltage: 3V; Mux Demux Ratio: 2:4; Nominal Supply Current: 1.3-11uA; On State Resistance: 3.9Ω; PositionCount: 1; Standoff Height: 0mm; TaMax_C: +125°C; TaMin_C: -40°C
Y1 = CMP-0004616-3: Crystal, 12 MHz, 18 pF, SMD; Manufacturer: Abracon Corporation; TaMin_C: -40°C; TaMax_C: 85°C; Frequency Stability: +/-30ppm; Frequency_Fixed: 12MHz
